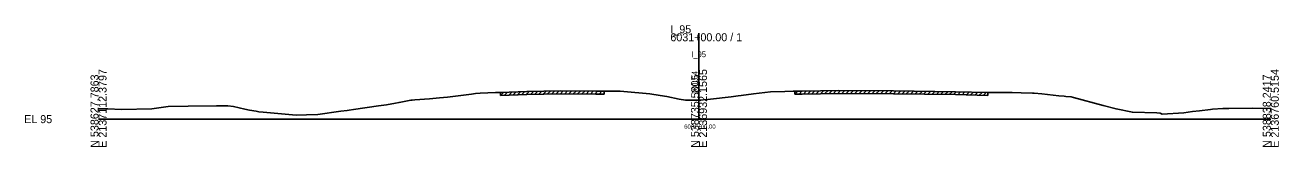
# Model space of a CAD drawing. Extents: x -12534 to 3403, y -1332 to 21983.
# Drawn here: x 974.3 to 1412.8, y 16990.3 to 17032.8 of the extents above; entities that cross this region are included whole.
import ezdxf

# ---------------------------------------------------------------- set-up
doc = ezdxf.new("R2010")
doc.units = 0
for name, color, linetype in [('RD_GPK_XS_Cell', 7, 'Continuous'), ('RD_XS_ExGround', 7, 'Continuous'), ('RD_XS_ExPaveRet', 7, 'Continuous'), ('RD_XS_TX_Baseline', 7, 'Continuous'), ('RD_XS_TX_Elev_EX', 7, 'Continuous'), ('RD_XS_TX_Station', 7, 'Continuous')]:
    doc.layers.add(name, color=color, linetype=linetype)

msp = doc.modelspace()

# ---------------------------------------------------------------- linework, layer by layer
at = {"layer": 'RD_GPK_XS_Cell'}
for p, q in [((1210, 17000), (1210, 17030)), ((1000, 17000), (1210, 17000)), ((1210, 17000), (1410, 17000))]:
    msp.add_line(p, q, dxfattribs=at)
at = {"layer": 'RD_XS_ExGround'}
msp.add_lwpolyline([(1000, 17003.62), (1003.3, 17003.64), (1007.98, 17003.4), (1018.65, 17003.59), (1024.41, 17004.46), (1031.31, 17004.52), (1041.22, 17004.67), (1045.21, 17004.64), (1047.16, 17004.42), (1051.11, 17003.52), (1052.82, 17003.13), (1055.16, 17002.74), (1056.06, 17002.59), (1057.63, 17002.47), (1069.12, 17001.44), (1072.72, 17001.54), (1076.74, 17001.61), (1084.73, 17002.74), (1086.96, 17003.06), (1087.68, 17003.15), (1089.13, 17003.36), (1097.95, 17004.6), (1100.72, 17005.03), (1103.92, 17005.6), (1105.09, 17005.84), (1109.22, 17006.58), (1109.72, 17006.65), (1110.58, 17006.7), (1115.8, 17007.13), (1119.26, 17007.4), (1122.01, 17007.73), (1130.43, 17008.74), (1131.89, 17008.91), (1133.53, 17009.03), (1138.79, 17009.33), (1140.54, 17009.29), (1149.76, 17009.63), (1161.65, 17009.89), (1173.88, 17009.74), (1176.85, 17009.73), (1181.87, 17009.8), (1182.39, 17009.79), (1183.67, 17009.64), (1192.87, 17008.81), (1196.46, 17008.27), (1198.76, 17007.93), (1203.09, 17006.96), (1205.3, 17006.64), (1209.91, 17006.63), (1213.06, 17006.89), (1214.02, 17006.98), (1221.27, 17007.84), (1223.68, 17008.14), (1224.76, 17008.29), (1229.13, 17008.84), (1235.07, 17009.51), (1240.06, 17009.68), (1242.89, 17009.75), (1243.52, 17009.75), (1246.14, 17009.77), (1258.87, 17010), (1278.07, 17009.85), (1299.73, 17009.55), (1311.05, 17009.3), (1313.73, 17009.29), (1319.5, 17009.26), (1322.67, 17009.16), (1326.65, 17009.06), (1327.22, 17009.02), (1329.94, 17008.8), (1335.83, 17008.18), (1337.73, 17007.97), (1338.33, 17007.89), (1340.12, 17007.75), (1341, 17007.51), (1351.34, 17004.73), (1355.88, 17003.57), (1361.59, 17002.4), (1370.11, 17002.15), (1371.31, 17002.14), (1372.03, 17001.79), (1379.64, 17002.26), (1382.67, 17002.63), (1385.09, 17002.87), (1388.89, 17003.34), (1389.66, 17003.51), (1393.21, 17003.68), (1395.35, 17003.73), (1403.69, 17003.8), (1410, 17003.66)], dxfattribs=at)
at = {"layer": 'RD_XS_ExPaveRet'}
for p, q in [((1140.54, 17008.29), (1141.58, 17009.33)), ((1140.54, 17008.29), (1140.54, 17009.29)), ((1140.54, 17008.29), (1149.76, 17008.63)), ((1142.04, 17008.35), (1143.08, 17009.39)), ((1143.54, 17008.4), (1144.58, 17009.44)), ((1145.04, 17008.46), (1146.08, 17009.49)), ((1146.54, 17008.51), (1147.58, 17009.55)), ((1148.04, 17008.57), (1149.08, 17009.6)), ((1149.54, 17008.62), (1150.57, 17009.65)), ((1149.76, 17008.63), (1161.65, 17008.89)), ((1151.04, 17008.66), (1152.07, 17009.68)), ((1152.54, 17008.69), (1153.57, 17009.71)), ((1154.04, 17008.72), (1155.07, 17009.74)), ((1155.54, 17008.76), (1156.57, 17009.78)), ((1157.04, 17008.79), (1158.07, 17009.81)), ((1158.54, 17008.82), (1159.57, 17009.84)), ((1160.04, 17008.85), (1161.07, 17009.88)), ((1161.54, 17008.89), (1162.54, 17009.88)), ((1161.65, 17008.89), (1173.88, 17008.74)), ((1163.04, 17008.87), (1164.03, 17009.86)), ((1164.54, 17008.85), (1165.53, 17009.84)), ((1166.04, 17008.84), (1167.03, 17009.82)), ((1167.54, 17008.82), (1168.53, 17009.8)), ((1169.04, 17008.8), (1170.03, 17009.79)), ((1170.54, 17008.78), (1171.53, 17009.77)), ((1172.04, 17008.76), (1173.03, 17009.75)), ((1173.54, 17008.74), (1174.54, 17009.74)), ((1173.88, 17008.74), (1176.85, 17008.73)), ((1175.04, 17008.74), (1176.04, 17009.73)), ((1176.85, 17009.73), (1176.85, 17008.73)), ((1243.52, 17008.75), (1244.53, 17009.76)), ((1243.52, 17008.75), (1243.52, 17009.75)), ((1243.52, 17008.75), (1246.14, 17008.77)), ((1245.02, 17008.76), (1246.03, 17009.77)), ((1246.14, 17008.77), (1258.87, 17009)), ((1246.52, 17008.78), (1247.54, 17009.79)), ((1248.02, 17008.8), (1249.04, 17009.82)), ((1249.52, 17008.83), (1250.54, 17009.85)), ((1251.02, 17008.86), (1252.04, 17009.88)), ((1252.52, 17008.89), (1253.54, 17009.9)), ((1254.02, 17008.91), (1255.04, 17009.93)), ((1255.52, 17008.94), (1256.54, 17009.96)), ((1257.02, 17008.97), (1258.04, 17009.99)), ((1258.52, 17008.99), (1259.53, 17010)), ((1258.87, 17009), (1278.07, 17008.85)), ((1260.02, 17008.99), (1261.02, 17009.98)), ((1261.52, 17008.98), (1262.52, 17009.97)), ((1263.02, 17008.97), (1264.02, 17009.96)), ((1264.52, 17008.96), (1265.52, 17009.95)), ((1266.02, 17008.94), (1267.02, 17009.94)), ((1267.52, 17008.93), (1268.52, 17009.93)), ((1269.02, 17008.92), (1270.02, 17009.91)), ((1270.52, 17008.91), (1271.52, 17009.9)), ((1272.02, 17008.9), (1273.02, 17009.89)), ((1273.52, 17008.89), (1274.52, 17009.88)), ((1275.02, 17008.87), (1276.02, 17009.87)), ((1276.52, 17008.86), (1277.52, 17009.85)), ((1278.02, 17008.85), (1279.01, 17009.84)), ((1278.07, 17008.85), (1299.73, 17008.55)), ((1279.52, 17008.83), (1280.51, 17009.82)), ((1281.02, 17008.81), (1282.01, 17009.8)), ((1282.52, 17008.79), (1283.51, 17009.78)), ((1284.02, 17008.77), (1285.01, 17009.76)), ((1285.52, 17008.75), (1286.51, 17009.73)), ((1287.02, 17008.73), (1288.01, 17009.71)), ((1288.52, 17008.71), (1289.51, 17009.69)), ((1290.02, 17008.69), (1291.01, 17009.67)), ((1291.52, 17008.67), (1292.51, 17009.65)), ((1293.02, 17008.65), (1294.01, 17009.63)), ((1294.52, 17008.63), (1295.51, 17009.61)), ((1296.02, 17008.6), (1297.01, 17009.59)), ((1297.52, 17008.58), (1298.51, 17009.57)), ((1299.02, 17008.56), (1300.01, 17009.55)), ((1299.73, 17008.55), (1311.05, 17008.3)), ((1300.52, 17008.54), (1301.5, 17009.51)), ((1302.02, 17008.5), (1303, 17009.48)), ((1303.52, 17008.47), (1304.5, 17009.45)), ((1305.02, 17008.44), (1306, 17009.41)), ((1306.52, 17008.4), (1307.5, 17009.38)), ((1308.02, 17008.37), (1309, 17009.35)), ((1309.52, 17008.34), (1310.5, 17009.32)), ((1311.05, 17009.3), (1311.05, 17008.3))]:
    msp.add_line(p, q, dxfattribs=at)

# ---------------------------------------------------------------- texts
at = {"layer": 'RD_GPK_XS_Cell'}
for s, p in [('I_95', (1200, 17030)), ('6031+00.00 / 1', (1200, 17027.2)), ('EL 95', (974, 16998.6))]:
    msp.add_text(s, height=2.8, dxfattribs=at).set_placement(p)
for s, p in [('N 538627.7863', (1000, 16990)), ('E 2137112.3797', (1002.8, 16990)), ('N 538735.5805', (1210, 16990)), ('E 2136932.1565', (1212.8, 16990)), ('N 538838.2417', (1410, 16990)), ('E 2136760.5154', (1412.8, 16990))]:
    msp.add_text(s, height=2.8, rotation=90, dxfattribs=at).set_placement(p)
at = {"layer": 'RD_XS_TX_Baseline'}
msp.add_text('I_95', height=2, dxfattribs=at).set_placement((1207.28, 17021.64))
at = {"layer": 'RD_XS_TX_Elev_EX'}
msp.add_text('101.64', height=2, rotation=90, dxfattribs=at).set_placement((1209.5, 17008.64))
at = {"layer": 'RD_XS_TX_Station'}
msp.add_text('6031+00.00', height=1.5, dxfattribs=at).set_placement((1204.83, 16996.64))

doc.saveas('drawing.dxf')
